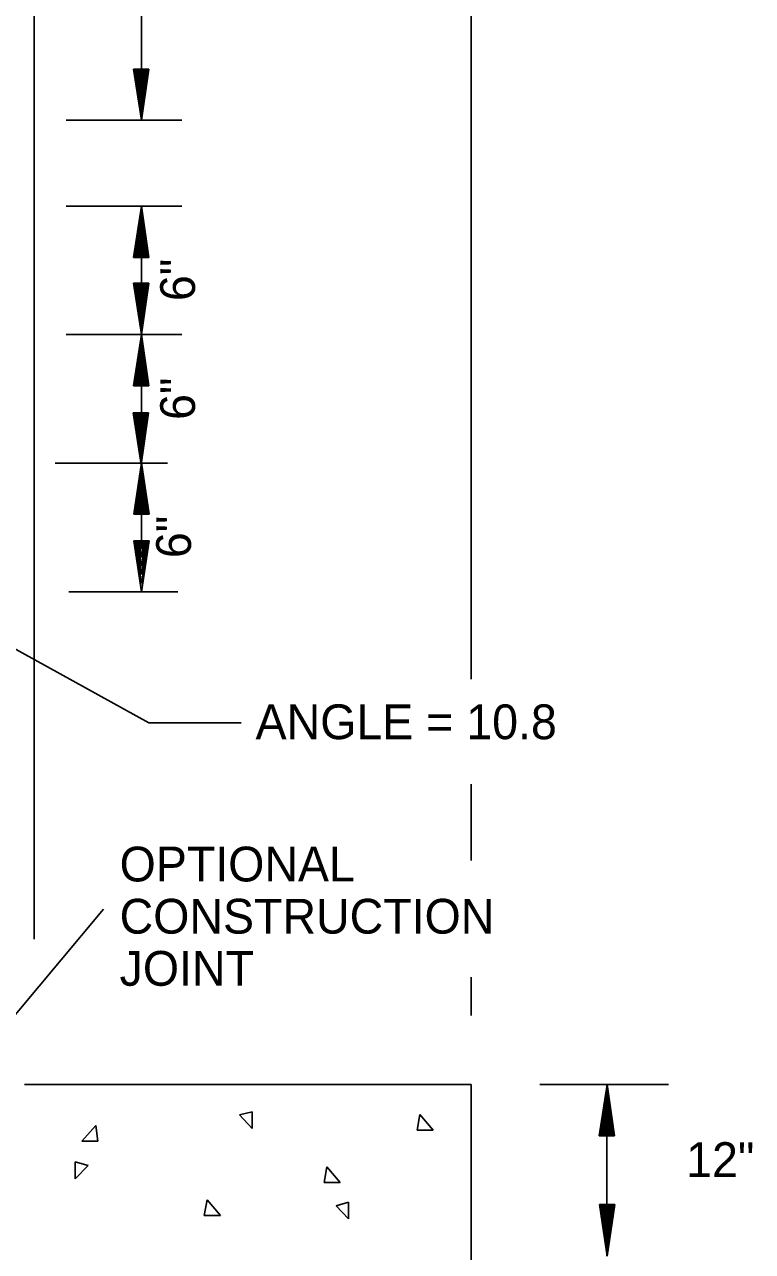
# Model space of a CAD drawing. Extents: x 714919 to 718439, y 1619644 to 1621844.
# Drawn here: x 715804.4 to 716021.3, y 1621100.6 to 1621466.5 of the extents above; entities that cross this region are included whole.
import ezdxf

# ---------------------------------------------------------------- set-up
doc = ezdxf.new("R2010")
doc.units = 0
doc.layers.add('R_Dimension', color=7, linetype='Continuous')
doc.layers.add('T_Drafting', color=7, linetype='Continuous')

msp = doc.modelspace()

# ---------------------------------------------------------------- linework, layer by layer
at = {"layer": 'R_Dimension'}
for p, q in [((715937.5, 1621563.18), (715937.5, 1621274.43)), ((715807.25, 1621529.75), (715807.25, 1621193.74)), ((715839.22, 1621482.23), (715839.22, 1621437.91)), ((715836.89, 1621453.2), (715839.22, 1621437.91)), ((715841.47, 1621453.2), (715836.89, 1621453.2)), ((715837.32, 1621453.2), (715839.22, 1621440.41)), ((715837.67, 1621453.2), (715839.22, 1621443.09)), ((715838.01, 1621453.2), (715839.22, 1621445.69)), ((715838.45, 1621453.2), (715839.22, 1621448.28)), ((715838.79, 1621453.2), (715839.22, 1621450.78)), ((715841.47, 1621453.2), (715839.22, 1621437.91)), ((715840, 1621453.2), (715839.22, 1621448.28)), ((715840.69, 1621453.2), (715839.22, 1621443.09)), ((715841.12, 1621453.2), (715839.22, 1621440.41)), ((715840.35, 1621453.2), (715839.22, 1621445.69)), ((715839.57, 1621453.2), (715839.22, 1621450.78)), ((715816.76, 1621437.91), (715851.32, 1621437.91)), ((715816.76, 1621412.33), (715851.32, 1621412.33)), ((715836.89, 1621397.04), (715839.22, 1621412.33)), ((715837.32, 1621397.04), (715839.22, 1621409.83)), ((715839.22, 1621412.33), (715839.22, 1621311.33)), ((715841.47, 1621397.04), (715839.22, 1621412.33)), ((715841.12, 1621397.04), (715839.22, 1621409.83)), ((715837.67, 1621397.04), (715839.22, 1621407.15)), ((715840.69, 1621397.04), (715839.22, 1621407.15)), ((715838.01, 1621397.04), (715839.22, 1621404.65)), ((715840.35, 1621397.04), (715839.22, 1621404.65)), ((715838.45, 1621397.04), (715839.22, 1621401.97)), ((715838.79, 1621397.04), (715839.22, 1621399.46)), ((715840, 1621397.04), (715839.22, 1621401.97)), ((715839.57, 1621397.04), (715839.22, 1621399.46)), ((715836.89, 1621397.04), (715841.47, 1621397.04)), ((715836.89, 1621389.35), (715839.22, 1621374.06)), ((715841.47, 1621389.35), (715836.89, 1621389.35)), ((715837.32, 1621389.35), (715839.22, 1621376.57)), ((715837.67, 1621389.35), (715839.22, 1621379.24)), ((715838.01, 1621389.35), (715839.22, 1621381.75)), ((715838.45, 1621389.35), (715839.22, 1621384.34)), ((715838.79, 1621389.35), (715839.22, 1621386.93)), ((715841.47, 1621389.35), (715839.22, 1621374.06)), ((715840, 1621389.35), (715839.22, 1621384.34)), ((715840.69, 1621389.35), (715839.22, 1621379.24)), ((715841.12, 1621389.35), (715839.22, 1621376.57)), ((715840.35, 1621389.35), (715839.22, 1621381.75)), ((715839.57, 1621389.35), (715839.22, 1621386.93)), ((715816.76, 1621374.06), (715851.32, 1621374.06)), ((715836.89, 1621358.68), (715839.22, 1621374.06)), ((715841.47, 1621358.68), (715839.22, 1621374.06)), ((715837.32, 1621358.68), (715839.22, 1621371.47)), ((715841.12, 1621358.68), (715839.22, 1621371.47)), ((715837.67, 1621358.68), (715839.22, 1621368.79)), ((715838.01, 1621358.68), (715839.22, 1621366.28)), ((715840.69, 1621358.68), (715839.22, 1621368.79)), ((715840.35, 1621358.68), (715839.22, 1621366.28)), ((715838.45, 1621358.68), (715839.22, 1621363.69)), ((715840, 1621358.68), (715839.22, 1621363.69)), ((715836.89, 1621358.68), (715841.47, 1621358.68)), ((715838.79, 1621358.68), (715839.22, 1621361.19)), ((715839.57, 1621358.68), (715839.22, 1621361.19)), ((715836.8, 1621350.65), (715839.14, 1621335.27)), ((715841.38, 1621350.65), (715836.8, 1621350.65)), ((715837.15, 1621350.65), (715839.14, 1621337.86)), ((715837.58, 1621350.65), (715839.14, 1621340.54)), ((715837.93, 1621350.65), (715839.14, 1621343.04)), ((715838.36, 1621350.65), (715839.14, 1621345.63)), ((715838.7, 1621350.65), (715839.14, 1621348.23)), ((715841.38, 1621350.65), (715839.14, 1621335.27)), ((715839.83, 1621350.65), (715839.14, 1621345.63)), ((715840.61, 1621350.65), (715839.14, 1621340.54)), ((715841.04, 1621350.65), (715839.14, 1621337.86)), ((715840.26, 1621350.65), (715839.14, 1621343.04)), ((715839.48, 1621350.65), (715839.14, 1621348.23)), ((715813.48, 1621335.7), (715821.94, 1621335.7)), ((715816.85, 1621335.7), (715835.59, 1621335.7)), ((715833.26, 1621335.7), (715847, 1621335.7)), ((715833.26, 1621335.7), (715839.4, 1621335.7)), ((715836.89, 1621335.44), (715836.89, 1621335.7)), ((715836.89, 1621335.44), (715836.89, 1621335.7)), ((715836.89, 1621335.44), (715836.89, 1621335.7)), ((715836.98, 1621320.41), (715839.22, 1621335.78)), ((715837.32, 1621320.41), (715839.22, 1621333.28)), ((715841.56, 1621320.41), (715839.22, 1621335.78)), ((715841.21, 1621320.41), (715839.22, 1621333.28)), ((715837.75, 1621320.41), (715839.22, 1621330.6)), ((715840.78, 1621320.41), (715839.22, 1621330.6)), ((715838.1, 1621320.41), (715839.22, 1621328.01)), ((715840.43, 1621320.41), (715839.22, 1621328.01)), ((715838.53, 1621320.41), (715839.22, 1621325.42)), ((715838.88, 1621320.41), (715839.22, 1621322.91)), ((715840, 1621320.41), (715839.22, 1621325.42)), ((715839.65, 1621320.41), (715839.22, 1621322.91)), ((715836.98, 1621320.41), (715841.56, 1621320.41)), ((715836.98, 1621312.54), (715839.22, 1621297.25)), ((715841.56, 1621312.54), (715836.98, 1621312.54)), ((715837.32, 1621312.54), (715839.22, 1621299.76)), ((715837.75, 1621312.54), (715839.22, 1621302.43)), ((715838.1, 1621312.54), (715839.22, 1621304.94)), ((715838.53, 1621312.54), (715839.22, 1621307.53)), ((715838.88, 1621312.54), (715839.22, 1621310.12)), ((715841.56, 1621312.54), (715839.22, 1621297.25)), ((715840, 1621312.54), (715839.22, 1621307.53)), ((715840.78, 1621312.54), (715839.22, 1621302.43)), ((715841.21, 1621312.54), (715839.22, 1621299.76)), ((715840.43, 1621312.54), (715839.22, 1621304.94)), ((715839.65, 1621312.54), (715839.22, 1621310.12)), ((715764.83, 1621300.45), (715841.47, 1621258.28)), ((715817.62, 1621297.34), (715828.68, 1621297.34)), ((715824.1, 1621297.34), (715828.68, 1621297.34)), ((715826.35, 1621297.34), (715828.08, 1621297.34)), ((715826.35, 1621297.34), (715850.11, 1621297.34)), ((715826.35, 1621297.34), (715832.48, 1621297.34)), ((715826.35, 1621297.34), (715832.48, 1621297.34)), ((715937.5, 1621271.22), (715937.5, 1621274.43)), ((715868.94, 1621258.28), (715841.47, 1621258.28)), ((715937.5, 1621217.19), (715937.5, 1621239.94)), ((715827.9, 1621202.64), (715785.4, 1621151.75)), ((715937.5, 1621170.99), (715937.5, 1621182.36)), ((715996.3, 1621150.37), (715958.02, 1621150.37)), ((715975.67, 1621135.08), (715978.01, 1621150.37)), ((715977.98, 1621099.22), (715977.98, 1621150.37)), ((715980.25, 1621135.08), (715978.01, 1621150.37)), ((715976.11, 1621135.08), (715978.01, 1621147.86)), ((715979.91, 1621135.08), (715978.01, 1621147.86)), ((715976.45, 1621135.08), (715978.01, 1621145.19)), ((715976.8, 1621135.08), (715978.01, 1621142.68)), ((715979.47, 1621135.08), (715978.01, 1621145.19)), ((715979.13, 1621135.08), (715978.01, 1621142.68)), ((715977.23, 1621135.08), (715978.01, 1621140.09)), ((715978.78, 1621135.08), (715978.01, 1621140.09)), ((715977.57, 1621135.08), (715978.01, 1621137.5)), ((715978.35, 1621135.08), (715978.01, 1621137.5)), ((715975.67, 1621135.08), (715980.25, 1621135.08)), ((715975.76, 1621114.6), (715978.01, 1621099.22)), ((715980.34, 1621114.6), (715975.76, 1621114.6)), ((715976.11, 1621114.6), (715978.01, 1621101.81)), ((715976.54, 1621114.6), (715978.01, 1621104.49)), ((715976.88, 1621114.6), (715978.01, 1621107)), ((715977.23, 1621114.6), (715978.01, 1621109.59)), ((715977.66, 1621114.6), (715978.01, 1621112.09)), ((715980.34, 1621114.6), (715978.01, 1621099.22)), ((715978.78, 1621114.6), (715978.01, 1621109.59)), ((715979.56, 1621114.6), (715978.01, 1621104.49)), ((715979.91, 1621114.6), (715978.01, 1621101.81)), ((715979.22, 1621114.6), (715978.01, 1621107)), ((715978.44, 1621114.6), (715978.01, 1621112.09))]:
    msp.add_line(p, q, dxfattribs=at)
at = {"layer": 'T_Drafting'}
for p, q in [((715937.5, 1621150.37), (715804.4, 1621150.37)), ((715937.5, 1621150.37), (715937.5, 1621065.62)), ((715872.23, 1621142.25), (715868.51, 1621141.3)), ((715868.51, 1621141.3), (715872.23, 1621137.24)), ((715872.23, 1621137.24), (715872.23, 1621142.25)), ((715922.25, 1621141.44), (715921.38, 1621136.78)), ((715926.22, 1621136.78), (715922.25, 1621141.44)), ((715821.51, 1621133.52), (715825.66, 1621138.19)), ((715825.66, 1621138.19), (715826.26, 1621133.52)), ((715921.38, 1621136.78), (715926.22, 1621136.78)), ((715826.26, 1621133.52), (715821.51, 1621133.52)), ((715819.52, 1621122.29), (715819.52, 1621127.3)), ((715819.52, 1621127.3), (715823.33, 1621126.26)), ((715823.33, 1621126.26), (715819.52, 1621122.29)), ((715894.54, 1621125.8), (715893.67, 1621121.14)), ((715898.51, 1621121.14), (715894.54, 1621125.8)), ((715893.67, 1621121.14), (715898.51, 1621121.14)), ((715858.84, 1621115.98), (715857.97, 1621111.32)), ((715862.81, 1621111.32), (715858.84, 1621115.98)), ((715900.99, 1621115.31), (715897.27, 1621114.19)), ((715897.27, 1621114.19), (715900.99, 1621110.3)), ((715900.99, 1621110.3), (715900.99, 1621115.31)), ((715857.97, 1621111.32), (715862.81, 1621111.32))]:
    msp.add_line(p, q, dxfattribs=at)

# ---------------------------------------------------------------- texts
at = {"layer": 'R_Dimension'}
for p in [(715855.21, 1621384), (715855.21, 1621348.57), (715854, 1621307.36)]:
    msp.add_text('6"', height=10.369, rotation=90, dxfattribs=at).set_placement(p)
for s, height, p in [('ANGLE = 10.8', 10.3685, (715873.26, 1621253.36)), ('OPTIONAL', 10.369, (715832.74, 1621210.94)), ('CONSTRUCTION', 10.3685, (715832.74, 1621195.38)), ('JOINT', 10.369, (715832.74, 1621179.83)), ('12"', 10.369, (716001.59, 1621122.81))]:
    msp.add_text(s, height=height, dxfattribs=at).set_placement(p)

doc.saveas('drawing.dxf')
